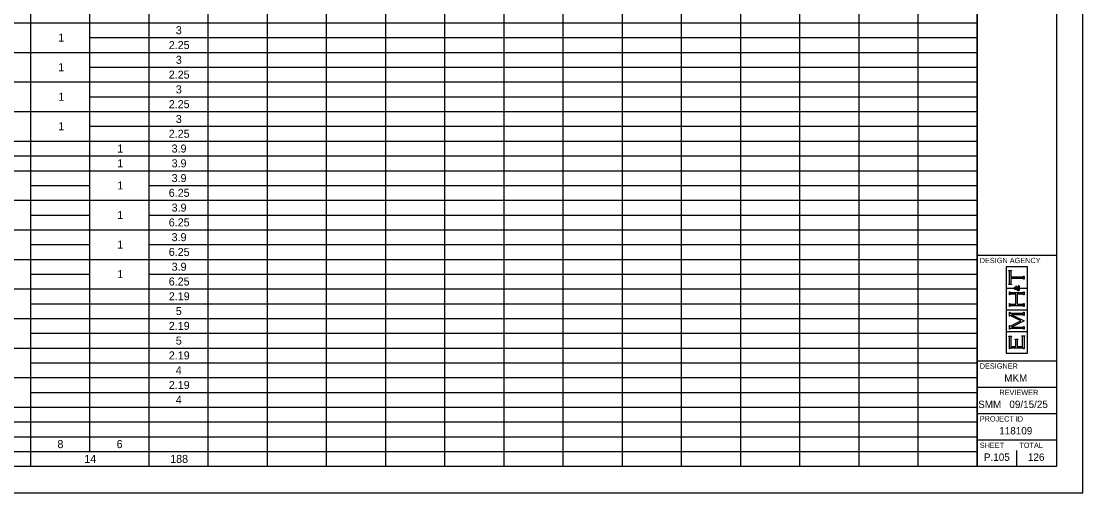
# Model space of a CAD drawing. Extents: x 0 to 34, y 0 to 22.
# Drawn here: x 13.91 to 34, y 0 to 8.93 of the extents above; entities that cross this region are included whole.
import ezdxf

# ---------------------------------------------------------------- set-up
doc = ezdxf.new("R2010")
doc.units = 0
for name, color, linetype in [('SH_Border', 7, 'Continuous'), ('SH_Cut_Line', 7, 'Continuous'), ('SH_Data', 7, 'Continuous'), ('SH_Text', 7, 'Continuous')]:
    doc.layers.add(name, color=color, linetype=linetype)

msp = doc.modelspace()

# ---------------------------------------------------------------- linework, layer by layer
at = {"layer": 'SH_Border'}
for p, q in [((32, 0.5), (32, 21.5)), ((32, 4.5), (33.5, 4.5)), ((32, 2.5), (33.5, 2.5)), ((32, 2), (33.5, 2)), ((32, 1.5), (33.5, 1.5)), ((32, 1), (33.5, 1))]:
    msp.add_line(p, q, dxfattribs=at)
msp.add_lwpolyline([(1.5, 21.5), (33.5, 21.5), (33.5, 0.5), (1.5, 0.5)], close=True, dxfattribs=at)
at = {"layer": 'SH_Cut_Line'}
msp.add_lwpolyline([(0, 0), (34, 0), (34, 22), (0, 22)], close=True, dxfattribs=at)
at = {"layer": 'SH_Data'}
for p, q in [((32.952, 4.279), (32.547, 4.279)), ((32.547, 4.279), (32.547, 3.875)), ((32.952, 3.875), (32.952, 4.279)), ((32.598, 4.204), (32.598, 4.211)), ((32.598, 4.211), (32.65, 4.211)), ((32.603, 4.203), (32.598, 4.204)), ((32.606, 4.201), (32.603, 4.203)), ((32.608, 4.199), (32.606, 4.201)), ((32.61, 4.196), (32.608, 4.199)), ((32.611, 4.192), (32.61, 4.196)), ((32.611, 4.187), (32.611, 4.192)), ((32.611, 3.968), (32.611, 4.187)), ((32.638, 4.196), (32.637, 4.192)), ((32.637, 4.192), (32.637, 4.187)), ((32.637, 4.187), (32.637, 4.093)), ((32.637, 4.093), (32.864, 4.093)), ((32.864, 4.061), (32.637, 4.061)), ((32.637, 4.061), (32.637, 3.968)), ((32.64, 4.199), (32.638, 4.196)), ((32.642, 4.201), (32.64, 4.199)), ((32.645, 4.203), (32.642, 4.201)), ((32.65, 4.204), (32.645, 4.203)), ((32.65, 4.211), (32.65, 4.204)), ((32.864, 4.093), (32.869, 4.093)), ((32.87, 4.061), (32.864, 4.061)), ((32.869, 4.093), (32.873, 4.094)), ((32.874, 4.06), (32.87, 4.061)), ((32.873, 4.094), (32.876, 4.096)), ((32.876, 4.059), (32.874, 4.06)), ((32.876, 4.096), (32.878, 4.097)), ((32.878, 4.057), (32.876, 4.059)), ((32.878, 4.097), (32.88, 4.101)), ((32.88, 4.053), (32.878, 4.057)), ((32.88, 4.101), (32.881, 4.106)), ((32.881, 4.048), (32.88, 4.053)), ((32.881, 4.106), (32.888, 4.106)), ((32.888, 4.048), (32.881, 4.048)), ((32.888, 4.106), (32.888, 4.048)), ((32.547, 3.875), (32.696, 3.875)), ((32.696, 3.869), (32.547, 3.869)), ((32.547, 3.869), (32.547, 3.465)), ((32.598, 3.95), (32.603, 3.951)), ((32.598, 3.944), (32.598, 3.95)), ((32.65, 3.944), (32.598, 3.944)), ((32.603, 3.951), (32.606, 3.953)), ((32.606, 3.953), (32.608, 3.955)), ((32.608, 3.955), (32.61, 3.958)), ((32.61, 3.958), (32.611, 3.962)), ((32.611, 3.962), (32.611, 3.968)), ((32.637, 3.968), (32.637, 3.962)), ((32.637, 3.962), (32.638, 3.958)), ((32.638, 3.958), (32.64, 3.955)), ((32.64, 3.955), (32.642, 3.953)), ((32.642, 3.953), (32.645, 3.951)), ((32.645, 3.951), (32.65, 3.95)), ((32.65, 3.95), (32.65, 3.944)), ((32.696, 3.875), (32.696, 3.869)), ((32.703, 3.879), (32.705, 3.883)), ((32.703, 3.873), (32.703, 3.879)), ((32.703, 3.868), (32.703, 3.873)), ((32.705, 3.863), (32.703, 3.868)), ((32.705, 3.883), (32.708, 3.887)), ((32.708, 3.858), (32.705, 3.863)), ((32.708, 3.887), (32.711, 3.89)), ((32.709, 3.879), (32.708, 3.876)), ((32.708, 3.876), (32.708, 3.873)), ((32.708, 3.873), (32.708, 3.869)), ((32.708, 3.869), (32.71, 3.866)), ((32.712, 3.853), (32.708, 3.858)), ((32.712, 3.881), (32.709, 3.879)), ((32.71, 3.866), (32.712, 3.864)), ((32.711, 3.89), (32.715, 3.892)), ((32.714, 3.883), (32.712, 3.881)), ((32.712, 3.864), (32.715, 3.862)), ((32.718, 3.85), (32.712, 3.853)), ((32.716, 3.884), (32.714, 3.883)), ((32.715, 3.892), (32.72, 3.892)), ((32.715, 3.862), (32.718, 3.861)), ((32.72, 3.884), (32.716, 3.884)), ((32.718, 3.861), (32.721, 3.861)), ((32.726, 3.85), (32.718, 3.85)), ((32.72, 3.892), (32.725, 3.892)), ((32.724, 3.884), (32.72, 3.884)), ((32.721, 3.861), (32.723, 3.861)), ((32.723, 3.861), (32.725, 3.862)), ((32.728, 3.882), (32.724, 3.884)), ((32.725, 3.892), (32.729, 3.89)), ((32.725, 3.862), (32.728, 3.862)), ((32.729, 3.85), (32.726, 3.85)), ((32.731, 3.88), (32.728, 3.882)), ((32.728, 3.862), (32.731, 3.863)), ((32.729, 3.89), (32.732, 3.887)), ((32.731, 3.85), (32.729, 3.85)), ((32.734, 3.877), (32.731, 3.88)), ((32.731, 3.863), (32.735, 3.865)), ((32.734, 3.851), (32.731, 3.85)), ((32.732, 3.887), (32.736, 3.883)), ((32.737, 3.872), (32.734, 3.877)), ((32.737, 3.852), (32.734, 3.851)), ((32.735, 3.865), (32.74, 3.867)), ((32.736, 3.883), (32.74, 3.878)), ((32.74, 3.867), (32.737, 3.872)), ((32.741, 3.853), (32.737, 3.852)), ((32.738, 3.893), (32.738, 3.922)), ((32.738, 3.922), (32.741, 3.922)), ((32.741, 3.893), (32.738, 3.893)), ((32.74, 3.878), (32.744, 3.869)), ((32.741, 3.922), (32.741, 3.918)), ((32.741, 3.918), (32.742, 3.915)), ((32.742, 3.896), (32.741, 3.895)), ((32.741, 3.895), (32.741, 3.893)), ((32.746, 3.855), (32.741, 3.853)), ((32.742, 3.915), (32.743, 3.913)), ((32.743, 3.897), (32.742, 3.896)), ((32.743, 3.913), (32.745, 3.911)), ((32.745, 3.899), (32.743, 3.897)), ((32.744, 3.869), (32.754, 3.875)), ((32.745, 3.911), (32.749, 3.908)), ((32.746, 3.899), (32.745, 3.899)), ((32.748, 3.899), (32.746, 3.899)), ((32.752, 3.844), (32.746, 3.855)), ((32.755, 3.899), (32.748, 3.899)), ((32.749, 3.908), (32.756, 3.904)), ((32.756, 3.86), (32.751, 3.857)), ((32.751, 3.857), (32.754, 3.852)), ((32.757, 3.837), (32.752, 3.844)), ((32.754, 3.875), (32.764, 3.881)), ((32.754, 3.852), (32.757, 3.848)), ((32.763, 3.895), (32.755, 3.899)), ((32.756, 3.904), (32.763, 3.9)), ((32.761, 3.863), (32.756, 3.86)), ((32.757, 3.848), (32.761, 3.845)), ((32.763, 3.833), (32.757, 3.837)), ((32.764, 3.865), (32.761, 3.863)), ((32.761, 3.845), (32.765, 3.843)), ((32.763, 3.9), (32.77, 3.896)), ((32.772, 3.887), (32.763, 3.895)), ((32.768, 3.829), (32.763, 3.833)), ((32.764, 3.881), (32.772, 3.887)), ((32.768, 3.867), (32.764, 3.865)), ((32.765, 3.843), (32.769, 3.841)), ((32.774, 3.872), (32.768, 3.867)), ((32.774, 3.827), (32.768, 3.829)), ((32.769, 3.841), (32.773, 3.841)), ((32.77, 3.896), (32.776, 3.891)), ((32.773, 3.841), (32.778, 3.841)), ((32.782, 3.878), (32.774, 3.872)), ((32.779, 3.827), (32.774, 3.827)), ((32.776, 3.891), (32.781, 3.895)), ((32.778, 3.841), (32.782, 3.843)), ((32.779, 3.923), (32.781, 3.926)), ((32.782, 3.922), (32.779, 3.923)), ((32.785, 3.827), (32.779, 3.827)), ((32.781, 3.926), (32.787, 3.924)), ((32.781, 3.895), (32.784, 3.898)), ((32.785, 3.921), (32.782, 3.922)), ((32.786, 3.873), (32.782, 3.878)), ((32.782, 3.843), (32.786, 3.846)), ((32.784, 3.898), (32.786, 3.901)), ((32.786, 3.919), (32.785, 3.921)), ((32.79, 3.829), (32.785, 3.827)), ((32.788, 3.917), (32.786, 3.919)), ((32.786, 3.901), (32.788, 3.904)), ((32.791, 3.886), (32.786, 3.881)), ((32.786, 3.881), (32.791, 3.876)), ((32.788, 3.869), (32.786, 3.873)), ((32.786, 3.846), (32.789, 3.849)), ((32.787, 3.924), (32.792, 3.921)), ((32.789, 3.914), (32.788, 3.917)), ((32.788, 3.904), (32.789, 3.908)), ((32.79, 3.867), (32.788, 3.869)), ((32.789, 3.911), (32.789, 3.914)), ((32.789, 3.908), (32.789, 3.911)), ((32.789, 3.849), (32.791, 3.853)), ((32.791, 3.864), (32.79, 3.867)), ((32.793, 3.834), (32.79, 3.829)), ((32.794, 3.89), (32.791, 3.886)), ((32.791, 3.876), (32.795, 3.87)), ((32.791, 3.861), (32.791, 3.864)), ((32.791, 3.859), (32.791, 3.861)), ((32.791, 3.853), (32.791, 3.859)), ((32.792, 3.921), (32.795, 3.918)), ((32.797, 3.838), (32.793, 3.834)), ((32.796, 3.894), (32.794, 3.89)), ((32.795, 3.918), (32.798, 3.914)), ((32.795, 3.87), (32.797, 3.866)), ((32.798, 3.897), (32.796, 3.894)), ((32.797, 3.866), (32.798, 3.861)), ((32.799, 3.844), (32.797, 3.838)), ((32.798, 3.914), (32.799, 3.91)), ((32.799, 3.901), (32.798, 3.897)), ((32.798, 3.861), (32.799, 3.857)), ((32.799, 3.91), (32.799, 3.905)), ((32.799, 3.905), (32.799, 3.901)), ((32.803, 3.869), (32.799, 3.875)), ((32.799, 3.875), (32.952, 3.875)), ((32.799, 3.857), (32.799, 3.852)), ((32.799, 3.852), (32.799, 3.844)), ((32.952, 3.869), (32.803, 3.869)), ((32.952, 3.465), (32.952, 3.869)), ((32.611, 3.749), (32.611, 3.807)), ((32.611, 3.807), (32.617, 3.807)), ((32.617, 3.749), (32.611, 3.749)), ((32.617, 3.807), (32.619, 3.802)), ((32.618, 3.754), (32.617, 3.749)), ((32.62, 3.758), (32.618, 3.754)), ((32.619, 3.802), (32.62, 3.798)), ((32.62, 3.798), (32.623, 3.797)), ((32.623, 3.76), (32.62, 3.758)), ((32.623, 3.797), (32.625, 3.795)), ((32.625, 3.761), (32.623, 3.76)), ((32.625, 3.795), (32.629, 3.794)), ((32.629, 3.762), (32.625, 3.761)), ((32.629, 3.794), (32.635, 3.794)), ((32.635, 3.762), (32.629, 3.762)), ((32.635, 3.794), (32.864, 3.794)), ((32.732, 3.762), (32.635, 3.762)), ((32.732, 3.572), (32.732, 3.762)), ((32.864, 3.762), (32.759, 3.762)), ((32.759, 3.762), (32.759, 3.572)), ((32.864, 3.794), (32.869, 3.794)), ((32.87, 3.762), (32.864, 3.762)), ((32.869, 3.794), (32.873, 3.795)), ((32.874, 3.761), (32.87, 3.762)), ((32.873, 3.795), (32.876, 3.797)), ((32.876, 3.76), (32.874, 3.761)), ((32.876, 3.797), (32.878, 3.798)), ((32.878, 3.758), (32.876, 3.76)), ((32.878, 3.798), (32.88, 3.802)), ((32.88, 3.754), (32.878, 3.758)), ((32.88, 3.802), (32.881, 3.807)), ((32.881, 3.749), (32.88, 3.754)), ((32.881, 3.807), (32.888, 3.807)), ((32.888, 3.749), (32.881, 3.749)), ((32.888, 3.807), (32.888, 3.749)), ((32.547, 3.465), (32.952, 3.465)), ((32.952, 3.459), (32.547, 3.459)), ((32.547, 3.459), (32.547, 3.055)), ((32.611, 3.527), (32.611, 3.585)), ((32.611, 3.585), (32.617, 3.585)), ((32.617, 3.527), (32.611, 3.527)), ((32.611, 3.345), (32.611, 3.418)), ((32.611, 3.418), (32.617, 3.418)), ((32.617, 3.585), (32.619, 3.58)), ((32.618, 3.532), (32.617, 3.527)), ((32.617, 3.418), (32.619, 3.412)), ((32.62, 3.536), (32.618, 3.532)), ((32.619, 3.58), (32.62, 3.576)), ((32.62, 3.576), (32.623, 3.574)), ((32.623, 3.537), (32.62, 3.536)), ((32.623, 3.574), (32.625, 3.573)), ((32.625, 3.539), (32.623, 3.537)), ((32.625, 3.573), (32.629, 3.572)), ((32.629, 3.54), (32.625, 3.539)), ((32.629, 3.572), (32.635, 3.572)), ((32.635, 3.54), (32.629, 3.54)), ((32.635, 3.572), (32.732, 3.572)), ((32.864, 3.54), (32.635, 3.54)), ((32.75, 3.5), (32.75, 3.5)), ((32.759, 3.572), (32.864, 3.572)), ((32.864, 3.572), (32.87, 3.572)), ((32.87, 3.54), (32.864, 3.54)), ((32.87, 3.572), (32.874, 3.573)), ((32.874, 3.539), (32.87, 3.54)), ((32.874, 3.573), (32.876, 3.574)), ((32.876, 3.538), (32.874, 3.539)), ((32.876, 3.574), (32.878, 3.576)), ((32.878, 3.536), (32.876, 3.538)), ((32.878, 3.576), (32.88, 3.58)), ((32.88, 3.532), (32.878, 3.536)), ((32.88, 3.58), (32.881, 3.585)), ((32.881, 3.527), (32.88, 3.532)), ((32.88, 3.412), (32.881, 3.418)), ((32.881, 3.585), (32.888, 3.585)), ((32.888, 3.527), (32.881, 3.527)), ((32.881, 3.418), (32.888, 3.418)), ((32.888, 3.585), (32.888, 3.527)), ((32.888, 3.418), (32.888, 3.36)), ((32.952, 3.055), (32.952, 3.459)), ((32.617, 3.345), (32.611, 3.345)), ((32.62, 3.352), (32.617, 3.345)), ((32.619, 3.412), (32.62, 3.409)), ((32.62, 3.409), (32.623, 3.407)), ((32.622, 3.355), (32.62, 3.352)), ((32.626, 3.355), (32.622, 3.355)), ((32.623, 3.407), (32.625, 3.405)), ((32.625, 3.405), (32.629, 3.405)), ((32.629, 3.355), (32.626, 3.355)), ((32.629, 3.405), (32.635, 3.405)), ((32.633, 3.353), (32.629, 3.355)), ((32.64, 3.35), (32.633, 3.353)), ((32.635, 3.405), (32.864, 3.405)), ((32.825, 3.257), (32.64, 3.35)), ((32.641, 3.165), (32.825, 3.257)), ((32.864, 3.373), (32.654, 3.373)), ((32.654, 3.373), (32.888, 3.255)), ((32.888, 3.255), (32.654, 3.138)), ((32.864, 3.405), (32.869, 3.405)), ((32.87, 3.373), (32.864, 3.373)), ((32.869, 3.405), (32.873, 3.405)), ((32.874, 3.372), (32.87, 3.373)), ((32.873, 3.405), (32.876, 3.407)), ((32.876, 3.37), (32.874, 3.372)), ((32.876, 3.407), (32.878, 3.409)), ((32.878, 3.369), (32.876, 3.37)), ((32.878, 3.409), (32.88, 3.412)), ((32.88, 3.365), (32.878, 3.369)), ((32.881, 3.36), (32.88, 3.365)), ((32.888, 3.36), (32.881, 3.36)), ((32.547, 3.055), (32.952, 3.055)), ((32.952, 3.049), (32.547, 3.049)), ((32.547, 3.049), (32.547, 2.645)), ((32.611, 3.096), (32.611, 3.168)), ((32.611, 3.168), (32.617, 3.168)), ((32.617, 3.096), (32.611, 3.096)), ((32.617, 3.168), (32.62, 3.162)), ((32.618, 3.102), (32.617, 3.096)), ((32.62, 3.105), (32.618, 3.102)), ((32.62, 3.162), (32.622, 3.158)), ((32.623, 3.107), (32.62, 3.105)), ((32.622, 3.158), (32.626, 3.158)), ((32.625, 3.109), (32.623, 3.107)), ((32.629, 3.109), (32.625, 3.109)), ((32.626, 3.158), (32.627, 3.158)), ((32.627, 3.158), (32.633, 3.161)), ((32.635, 3.109), (32.629, 3.109)), ((32.633, 3.161), (32.641, 3.165)), ((32.864, 3.109), (32.635, 3.109)), ((32.654, 3.138), (32.864, 3.138)), ((32.864, 3.138), (32.869, 3.138)), ((32.87, 3.109), (32.864, 3.109)), ((32.869, 3.138), (32.873, 3.139)), ((32.874, 3.109), (32.87, 3.109)), ((32.873, 3.139), (32.876, 3.141)), ((32.876, 3.107), (32.874, 3.109)), ((32.876, 3.141), (32.878, 3.143)), ((32.878, 3.105), (32.876, 3.107)), ((32.878, 3.143), (32.88, 3.146)), ((32.88, 3.102), (32.878, 3.105)), ((32.88, 3.146), (32.881, 3.151)), ((32.881, 3.096), (32.88, 3.102)), ((32.881, 3.151), (32.888, 3.151)), ((32.888, 3.096), (32.881, 3.096)), ((32.888, 3.151), (32.888, 3.096)), ((32.952, 2.645), (32.952, 3.049)), ((32.598, 2.962), (32.598, 2.969)), ((32.598, 2.969), (32.65, 2.969)), ((32.603, 2.961), (32.598, 2.962)), ((32.606, 2.959), (32.603, 2.961)), ((32.608, 2.957), (32.606, 2.959)), ((32.61, 2.955), (32.608, 2.957)), ((32.611, 2.951), (32.61, 2.955)), ((32.611, 2.945), (32.611, 2.951)), ((32.611, 2.725), (32.611, 2.945)), ((32.64, 2.957), (32.638, 2.955)), ((32.638, 2.955), (32.638, 2.951)), ((32.638, 2.951), (32.638, 2.945)), ((32.638, 2.945), (32.638, 2.77)), ((32.642, 2.959), (32.64, 2.957)), ((32.645, 2.961), (32.642, 2.959)), ((32.65, 2.962), (32.645, 2.961)), ((32.65, 2.969), (32.65, 2.962)), ((32.719, 2.902), (32.719, 2.908)), ((32.719, 2.908), (32.772, 2.908)), ((32.724, 2.901), (32.719, 2.902)), ((32.728, 2.899), (32.724, 2.901)), ((32.729, 2.896), (32.728, 2.899)), ((32.731, 2.894), (32.729, 2.896)), ((32.732, 2.89), (32.731, 2.894)), ((32.732, 2.884), (32.732, 2.89)), ((32.732, 2.77), (32.732, 2.884)), ((32.76, 2.894), (32.759, 2.89)), ((32.759, 2.89), (32.759, 2.884)), ((32.759, 2.884), (32.759, 2.77)), ((32.761, 2.896), (32.76, 2.894)), ((32.763, 2.899), (32.761, 2.896)), ((32.767, 2.901), (32.763, 2.899)), ((32.772, 2.902), (32.767, 2.901)), ((32.772, 2.908), (32.772, 2.902)), ((32.848, 2.965), (32.848, 2.972)), ((32.848, 2.972), (32.901, 2.972)), ((32.853, 2.964), (32.848, 2.965)), ((32.857, 2.962), (32.853, 2.964)), ((32.859, 2.96), (32.857, 2.962)), ((32.86, 2.958), (32.859, 2.96)), ((32.861, 2.953), (32.86, 2.958)), ((32.861, 2.948), (32.861, 2.953)), ((32.861, 2.77), (32.861, 2.948)), ((32.889, 2.957), (32.888, 2.953)), ((32.888, 2.953), (32.888, 2.948)), ((32.888, 2.948), (32.888, 2.725)), ((32.891, 2.96), (32.889, 2.957)), ((32.892, 2.962), (32.891, 2.96)), ((32.896, 2.964), (32.892, 2.962)), ((32.901, 2.965), (32.896, 2.964)), ((32.901, 2.972), (32.901, 2.965)), ((32.547, 2.645), (32.952, 2.645)), ((32.617, 2.725), (32.611, 2.725)), ((32.619, 2.73), (32.617, 2.725)), ((32.62, 2.734), (32.619, 2.73)), ((32.623, 2.735), (32.62, 2.734)), ((32.625, 2.737), (32.623, 2.735)), ((32.629, 2.738), (32.625, 2.737)), ((32.635, 2.738), (32.629, 2.738)), ((32.864, 2.738), (32.635, 2.738)), ((32.638, 2.77), (32.732, 2.77)), ((32.759, 2.77), (32.861, 2.77)), ((32.87, 2.738), (32.864, 2.738)), ((32.874, 2.737), (32.87, 2.738)), ((32.876, 2.735), (32.874, 2.737)), ((32.878, 2.734), (32.876, 2.735)), ((32.88, 2.73), (32.878, 2.734)), ((32.881, 2.725), (32.88, 2.73)), ((32.888, 2.725), (32.881, 2.725)), ((32.375, 0.675), (32.375, 0.675)), ((32.75, 0.5), (32.75, 0.8))]:
    msp.add_line(p, q, dxfattribs=at)
at = {"layer": 'SH_Text'}
for p, q in [((14.082, 21.499), (14.082, 0.502)), ((15.202, 21.499), (15.202, 0.782)), ((16.322, 21.499), (16.322, 0.502)), ((17.442, 21.499), (17.442, 0.502)), ((18.562, 21.499), (18.562, 0.502)), ((19.681, 21.499), (19.681, 0.502)), ((20.801, 21.499), (20.801, 0.502)), ((21.921, 21.499), (21.921, 0.502)), ((23.041, 21.499), (23.041, 0.502)), ((24.161, 21.499), (24.161, 0.502)), ((25.281, 21.499), (25.281, 0.502)), ((26.401, 21.499), (26.401, 0.502)), ((27.521, 21.499), (27.521, 0.502)), ((28.64, 21.499), (28.64, 0.502)), ((29.76, 21.499), (29.76, 0.502)), ((30.88, 21.499), (30.88, 0.502)), ((32, 21.499), (32, 0.502)), ((1.5, 8.901), (32, 8.901)), ((15.202, 8.621), (32, 8.621)), ((1.5, 8.341), (32, 8.341)), ((15.202, 8.061), (32, 8.061)), ((1.5, 7.781), (32, 7.781)), ((15.202, 7.501), (32, 7.501)), ((1.5, 7.221), (32, 7.221)), ((15.202, 6.941), (32, 6.941)), ((1.5, 6.661), (32, 6.661)), ((1.5, 6.381), (32, 6.381)), ((1.5, 6.101), (32, 6.101)), ((14.082, 5.821), (15.202, 5.821)), ((16.322, 5.821), (32, 5.821)), ((1.5, 5.541), (32, 5.541)), ((14.082, 5.261), (15.202, 5.261)), ((16.322, 5.261), (32, 5.261)), ((1.5, 4.981), (32, 4.981)), ((14.082, 4.701), (15.202, 4.701)), ((16.322, 4.701), (32, 4.701)), ((1.5, 4.421), (32, 4.421)), ((14.082, 4.141), (15.202, 4.141)), ((16.322, 4.141), (32, 4.141)), ((1.5, 3.861), (32, 3.861)), ((14.082, 3.582), (32, 3.582)), ((1.5, 3.302), (32, 3.302)), ((14.082, 3.022), (32, 3.022)), ((1.5, 2.742), (32, 2.742)), ((14.082, 2.462), (32, 2.462)), ((1.5, 2.182), (32, 2.182)), ((14.082, 1.902), (32, 1.902)), ((1.5, 1.622), (32, 1.622)), ((1.5, 1.342), (32, 1.342)), ((10.722, 1.062), (32, 1.062)), ((1.5, 0.782), (32, 0.782)), ((1.5, 0.502), (32, 0.502))]:
    msp.add_line(p, q, dxfattribs=at)

# ---------------------------------------------------------------- texts
at = {"layer": 'SH_Data'}
for s, height, p in [('DESIGN AGENCY', 0.1, (32.05, 4.35)), ('DESIGNER', 0.1, (32.05, 2.35)), ('MKM', 0.14, (32.513, 2.105)), ('REVIEWER', 0.1, (32.422, 1.85)), ('SMM', 0.14, (32.02, 1.605)), ('09/15/25', 0.14, (32.611, 1.605)), ('PROJECT ID', 0.1, (32.05, 1.35)), ('118109', 0.14, (32.42, 1.105)), ('SHEET', 0.1, (32.05, 0.85)), ('TOTAL', 0.1, (32.8, 0.85)), ('P.105', 0.14, (32.129, 0.605)), ('126', 0.14, (32.962, 0.605))]:
    msp.add_text(s, height=height, dxfattribs=at).set_placement(p)
at = {"layer": 'SH_Text'}
for s, height, p in [('1', 0.152, (14.607, 8.545)), ('3', 0.152, (16.833, 8.685)), ('2.25', 0.1515, (16.7, 8.405)), ('3', 0.152, (16.833, 8.125)), ('1', 0.152, (14.607, 7.985)), ('2.25', 0.1515, (16.7, 7.845)), ('3', 0.152, (16.833, 7.565)), ('1', 0.152, (14.607, 7.425)), ('2.25', 0.1515, (16.7, 7.285)), ('3', 0.152, (16.833, 7.005)), ('1', 0.152, (14.607, 6.865)), ('2.25', 0.1515, (16.7, 6.725)), ('1', 0.152, (15.726, 6.445)), ('3.9', 0.1515, (16.754, 6.445)), ('1', 0.152, (15.726, 6.165)), ('3.9', 0.1515, (16.754, 6.165)), ('3.9', 0.1515, (16.754, 5.885)), ('1', 0.152, (15.726, 5.745)), ('6.25', 0.1515, (16.7, 5.606)), ('3.9', 0.1515, (16.754, 5.326)), ('1', 0.152, (15.726, 5.186)), ('6.25', 0.1515, (16.7, 5.046)), ('3.9', 0.1515, (16.754, 4.766)), ('1', 0.152, (15.726, 4.626)), ('6.25', 0.1515, (16.7, 4.486)), ('3.9', 0.1515, (16.754, 4.206)), ('1', 0.152, (15.726, 4.066)), ('6.25', 0.1515, (16.7, 3.926)), ('2.19', 0.1515, (16.701, 3.646)), ('5', 0.152, (16.833, 3.366)), ('2.19', 0.1515, (16.701, 3.086)), ('5', 0.152, (16.833, 2.806)), ('2.19', 0.1515, (16.701, 2.526)), ('4', 0.152, (16.833, 2.246)), ('2.19', 0.1515, (16.701, 1.966)), ('4', 0.152, (16.833, 1.686)), ('8', 0.152, (14.593, 0.846)), ('6', 0.152, (15.713, 0.846)), ('14', 0.1515, (15.101, 0.566)), ('188', 0.1515, (16.727, 0.566))]:
    msp.add_text(s, height=height, dxfattribs=at).set_placement(p)

doc.saveas('drawing.dxf')
